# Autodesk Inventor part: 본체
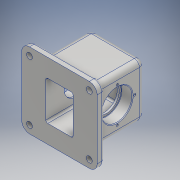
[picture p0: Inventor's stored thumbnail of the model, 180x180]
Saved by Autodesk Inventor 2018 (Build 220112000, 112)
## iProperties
Created: 2022-07
Part Number: 본체
Material: 알루미늄 6061
Document SubType Name: Modeling
Designer: home
Density: 2.7 g/cm^3
Appearance: 알루미늄 - 평지
Mass: 1059.56 g
Surface Area: 722.413 cm^2
Volume: 392.431 cm^3
Author: home
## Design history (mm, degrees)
sketch "스케치1"
  geometry: L1 (58, -58)-(-58, -58); L2 (-58, -58)-(-58, 58); L3 (-58, 58)-(58, 58); L4 (58, 58)-(58, -58); L5 (58, -58)-(-58, 58); 2 further points
  constraints: 10 end point, 2 coincident, 2 parallel, 1 horizontal, 1 midpoint, 1 perpendicular
  dimensions: "d0" = 116 distance of L1.end L2.end; "d1" = 116 distance of L1.start L1.end
extrude "돌출1" new body sketch "스케치1" distance "d2" = 10; taper "d3" = 0 deg
sketch "스케치2"
  geometry: L1 (-41, -41)-(41, -41); L2 (41, -41)-(41, 41); L3 (41, 41)-(-41, 41); L4 (-41, 41)-(-41, -41); L5 (-41, -41)-(41, 41); 3 further points
  constraints: 10 end point, 2 midpoint, 2 parallel, 1 coincident, 1 horizontal, 1 perpendicular, 1 vertical alignment
  dimensions: "d4" = 82 distance of L2.end L3.end; "d5" = 82 distance of L3.end L1.start
extrude "돌출2" join sketch "스케치2" distance "d6" = 80; taper "d7" = 0 deg
sketch "스케치4"
  geometry: L1 (21, -30)-(-21, -30); L2 (-21, -30)-(-21, 30); L3 (-21, 30)-(21, 30); L4 (21, 30)-(21, -30); 3 further points
  constraints: 8 end point, 2 midpoint, 2 parallel, 1 horizontal, 1 horizontal alignment, 1 perpendicular, 1 vertical alignment
  dimensions: "d8" = 60 distance of L1.end L2.end; "d9" = 42 distance of L1.start L1.end
extrude "돌출3" cut sketch "스케치4" distance "d10" = 80; taper "d11" = 0 deg
sketch "스케치6"
  geometry: L1 (99, -10)-(-17, -10) reference; 3 further points
  constraints: 1 midpoint, 1 vertical alignment
  dimensions: "d24" = 48 distance from line of L1 point (41, 38)
hole "구멍2" sketch "스케치6" at (41, 38) diameter "d25" = 40; stored, may be unused: countersink angle "d29" = 90 deg, drill point angle "d31" = 118 deg; dims "d26" = 6, "d27" = 47, "d28" = 17, "d30" = 20
fillet "모깎기2" dims "d32" = 0.6
chamfer "모따기2" distance "d33" = 1; stored, may be unused: second distance "d34" = 2, angle "d35" = 45 deg
fillet "모깎기3" dims "d36" = 0.6
chamfer "모따기3" distance "d37" = 1; stored, may be unused: second distance "d38" = 2, angle "d39" = 45 deg
sketch "스케치7"
  geometry: C1 r 24.5 at (41, 38) reference; 2 further points
  constraints: 1 vertical alignment
  dimensions: "d40" = 27 distance of C1.centre point (41, 65)
hole "구멍3" sketch "스케치7" at (41, 65) diameter "d41" = 3.242; stored, may be unused: countersink angle "d45" = 90 deg, drill point angle "d47" = 118 deg; dims "d42" = 8, "d43" = 47, "d44" = 17, "d46" = 10
fillet "모깎기4" dims "d51" = 8
fillet "모깎기5" dims "d52" = 12
fillet "모깎기6" dims "d53" = 3
fillet "모깎기7" dims "d54" = 3
sketch "스케치8"
  geometry: A1 r 12 centre (46, -46) between (46, -58) and (58, -46) reference; A2 r 12 centre (-46, -46) between (-58, -46) and (-46, -58) reference; A3 r 12 centre (-46, 46) between (-46, 58) and (-58, 46) reference; A4 r 12 centre (46, 46) between (58, 46) and (46, 58) reference; 1 further point
hole "구멍4" sketch "스케치8" at (46, -46), (-46, -46), (-46, 46), (46, 46) diameter "d55" = 9; stored, may be unused: countersink angle "d59" = 90 deg, drill point angle "d61" = 118 deg; dims "d56" = 8, "d57" = 47, "d58" = 17, "d60" = 10
node "작업 평면1"
sketch "스케치9"
  geometry: C1 r 7.5 at (0, 0); 1 further point
  constraints: 1 centre point, 1 coincident
  dimensions: "d63" = 15 diameter of C1
extrude "돌출4" join sketch "스케치9" stored distance "d64" = 80; taper "d65" = 0 deg
sketch "스케치10"
  geometry: C1 r 7.5 at (0, 0) reference; 1 further point
hole "구멍5" sketch "스케치10" at (0, 0) diameter "d66" = 4.917; stored, may be unused: countersink angle "d70" = 90 deg, drill point angle "d72" = 118 deg; dims "d67" = 20, "d68" = 47, "d69" = 17, "d71" = 17.1
fillet "모깎기8" dims "d73" = 8
fillet "모깎기9" dims "d74" = 3
sketch "스케치12"
  geometry: L1 (66, 77)-(0, 77) reference; L2 (79, -13)-(-13, -13) reference; 3 further points
  constraints: 1 midpoint, 1 vertical alignment, 1 other
  dimensions: "d78" = 48 distance from line of point (33, 35) L2
feature "엠보싱2" sketch "스케치12" dims "d0" = 116, "d1" = 116, "d9" = 42, "d79" = 0.5, "d80" = 0
fillet "모깎기10" dims "d81" = 3
node "솔리드1"
mirror "미러1"
pattern_circular "원형 패턴1" dims angle "d49" = 360 deg
mirror "미러2"
node "투영된 루프1"
other parameters: "d62" = 4
